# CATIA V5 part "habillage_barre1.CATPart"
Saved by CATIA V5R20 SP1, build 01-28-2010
Part number: habillage_barre1
Bounding box of the stored display mesh (mm): x -40 to -20, y -210.207 to 39.987, z -39.989 to 81.803
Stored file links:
  C:\Users\patrice\Desktop\IFMa\Semestre 3\IAO\projet iao\iao\habillage_barre1.CATPart
  C:\Users\patrice\Desktop\IFMa\Semestre 3\IAO\projet iao\iao\pcabanel.CATProduct
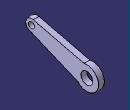
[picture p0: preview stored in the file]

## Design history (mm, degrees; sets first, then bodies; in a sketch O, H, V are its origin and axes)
External parameters (linked from other documents)
  External.AC = 200 mm
Set1
  Plane1: linked copy from another document
  Point1 "C": linked copy from another document
  Point2 "A": linked copy from another document
  Line1: linked copy from another document
Body1 (main body)
  Sketch1 on Plane1, origin (0, 0, 0), H (0, 1, 0), V (0, 0, 1)
    line L1 (-30.5466, -25.8245) -> (-196.8893, 42.9512)
    arc A1 centre (-190.2113, 61.8034) radius 20 from (-196.8893, 42.9512) to (-184.5329, 80.9804) cw
    point P3 (-190.2113, 61.8034)
    line L2 (-184.5329, 80.9804) -> (-9.5334, 38.8473)
    arc A2 centre (0, 0) radius 40 from (-9.5334, 38.8473) to (-30.5466, -25.8245) cw
    point P6 (0, 0)
    reference projected point E1 (-190.2113, 61.8034) from Point1
    reference projected point E2 (0, 0) from Point2
    construction line L3 (-9.5334, 38.8473) -> (-30.5466, -25.8245)
    reference projected line E3 (0, 0) -> (-190.2113, 61.8034) from Line1
    radius A1 = 20 {= External.AC /10}
    radius A2 = 40 {= External.AC /5}
    length L2 = 180 {= 0.9*External.AC}
    length L1 = 180 {= 0.9*External.AC}
    length L3 = 68 {= 0.34*External.AC}
    coincidence: P3 E1, P6 E2
    perpendicularity: E3 L3
  Pad1: profile Sketch1, direction (-1, 0, 0), length 40 {= External.AC /5}, opposite side length -20 {= -External.AC /10}
  Sketch2 on start face of Pad1, origin (-20, -16.2743, 9.2589), H (0, 1, 0), V (0, 0, 1)
    point P1 (-173.937, 52.5445)
    reference projected point E1 (-173.937, 52.5445) from Point1
    coincidence: P1 E1
  Hole1: placed by Sketch2, at (-20, -190.2113, 61.8034) direction (-1, 0, 0), diameter 20 {= External.AC /10}, through (limit type 6)
  Sketch3 on start face of Pad1, origin (-20, -6.5058, -0.404), H (0, 1, 0), V (0, 0, 1)
    point P1 (6.5058, 0.404)
    reference projected point E1 (6.5058, 0.404) from Point2
    coincidence: P1 E1
  Hole2: placed by Sketch3, at (-20, 0, 0) direction (-1, 0, 0), diameter 40 {= External.AC /5}, through (limit type 6)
